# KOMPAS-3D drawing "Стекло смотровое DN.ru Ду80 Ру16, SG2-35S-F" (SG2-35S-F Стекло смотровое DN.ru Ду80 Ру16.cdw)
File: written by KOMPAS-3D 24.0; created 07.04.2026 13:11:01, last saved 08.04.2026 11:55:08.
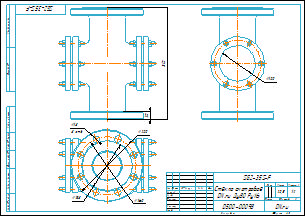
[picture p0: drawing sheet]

Document properties: Автор: Main; Форматы листов документа: A3; Полное имя файла: SG2-35S-F Стекло смотровое DN.ru Ду80 Ру16.m3d; Масса: 20.5; Наименование: Стекло смотровое DN.ru Ду80 Ру16; Количество листов документа: 1; Примечание: D500-00098

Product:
- Body: Тело 1  | qty 1
    Масса: 19.954238
- Part/product: Стекло смотровое DN.ru Ду80 Ру16  | designation SG2-35S-F
    Масса: 20.5
    Раздел спецификации: Прочие изделия
    Примечание: D500-00098

Views: Вид 1, Снизу, Проекционный вид 2, Проекционный вид 3
Referenced files in D:\DN.ru Аутсерс\Стекло смотровое DN.ru\Стекло смотровое DN.ru SG2-34G-F тип В ГОСТ 21836-2021 Ду100 Ру16, углеродистая сталь, фланцевое\: SG2-34G-F тип В Стекло смотровое DN.ru Ду100 Ру16.m3d, SG2-34G-F тип ВСтекло смотровое DN.ru Ду100 Ру16.cdw
Referenced files in D:\DN.ru Аутсерс\Стекло смотровое DN.ru\SG2-35S-F Стекло смотровое DN.ru Ду80 Ру16\: SG2-35S-F Стекло смотровое DN.ru Ду80 Ру16.m3d
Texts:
  SG2-35S-F
  Стекло смотровое
  DN.ru Ду80 Ру16
  Стекло смотровое DN.ru Ду80 Ру16
  SG2-35S-F Стекло смотровое DN.ru Ду80 Ру16
Dimensions and other numbers on the sheet: 0; 3; 2; 4; 310; 20; 200; 138; 18; 8 отв.; 160; 100; 1:2; 1; 20,5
